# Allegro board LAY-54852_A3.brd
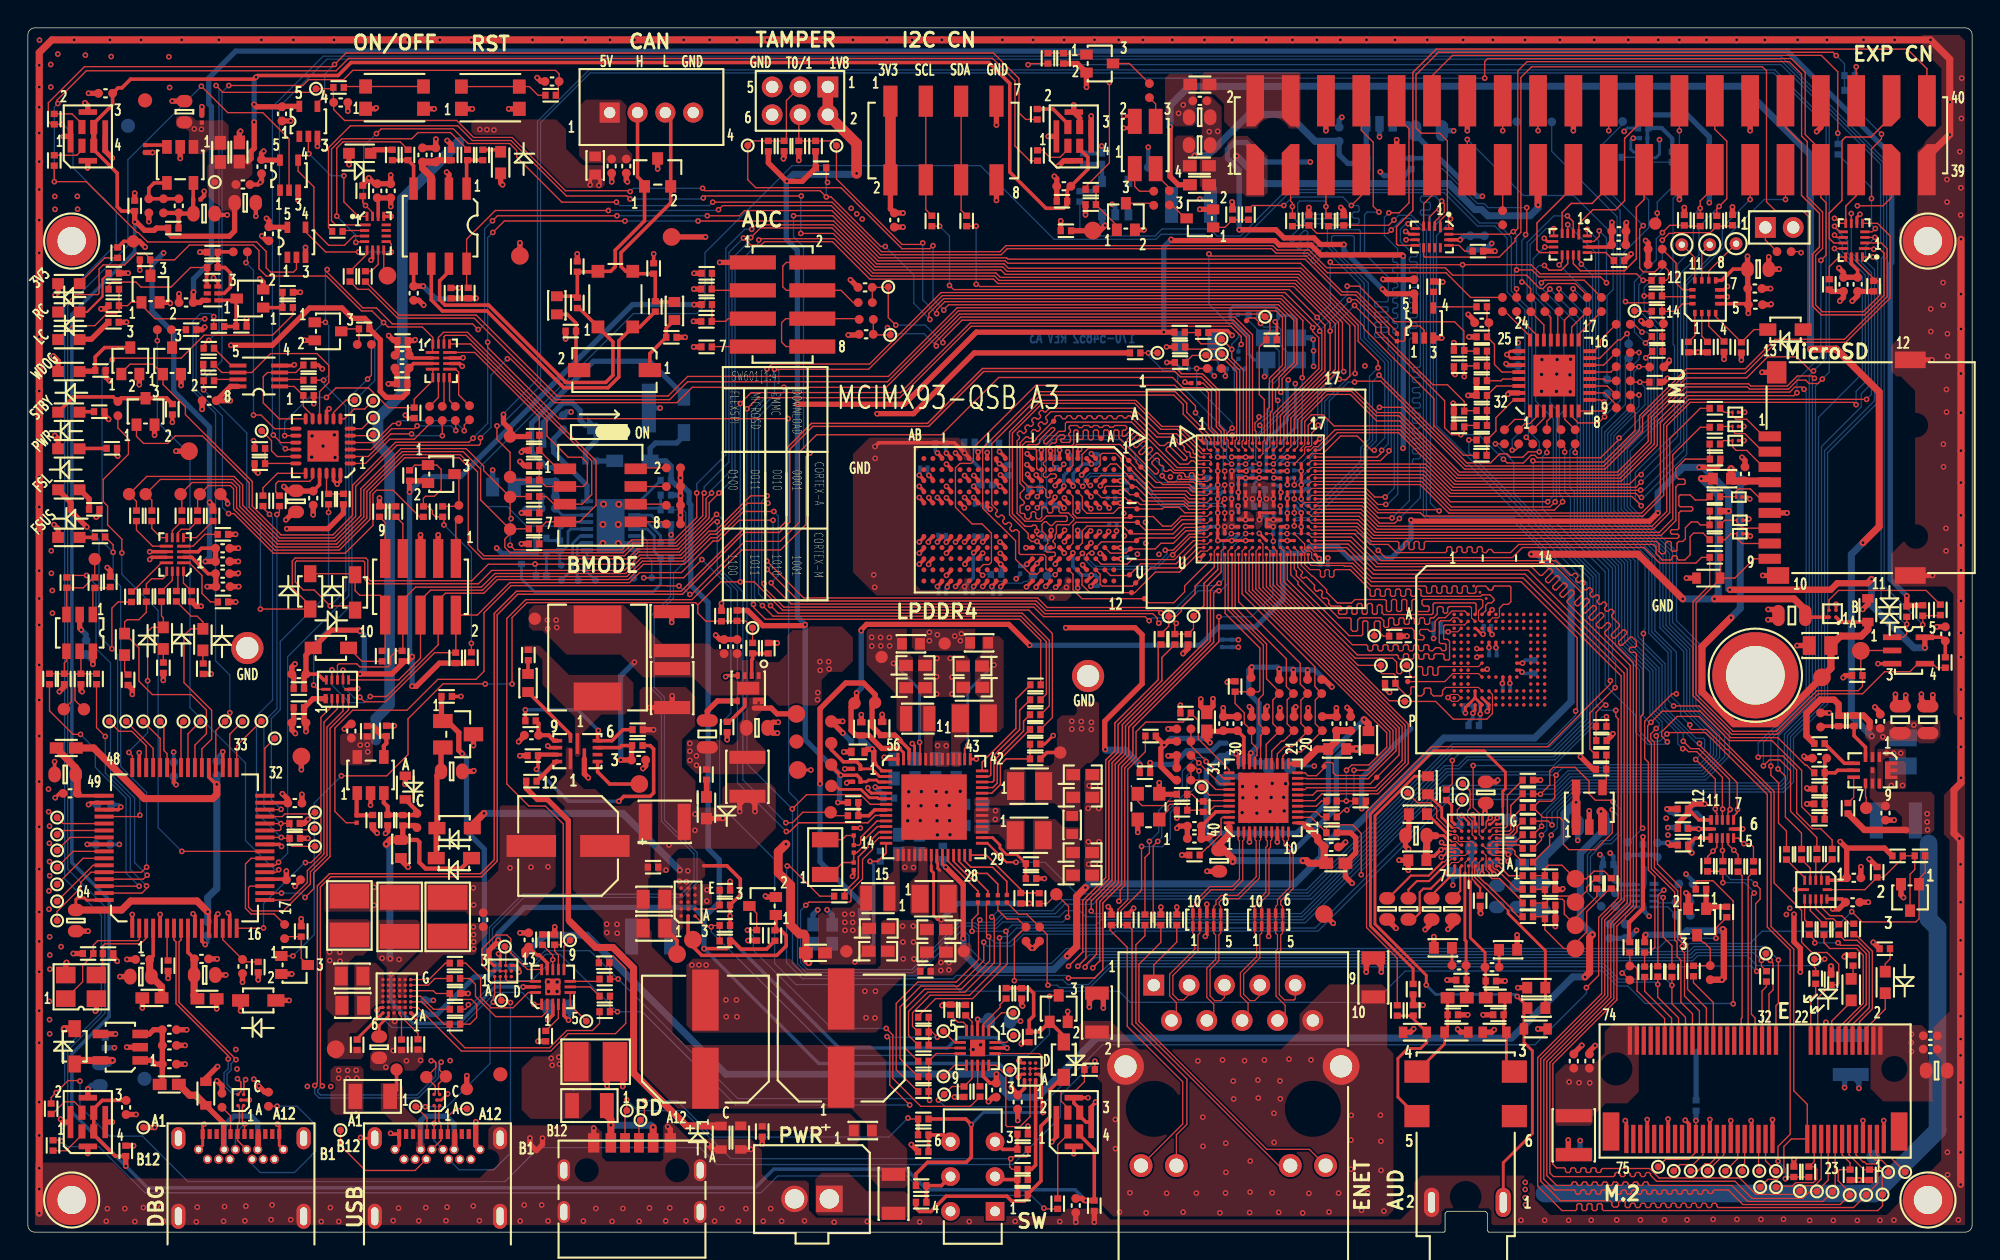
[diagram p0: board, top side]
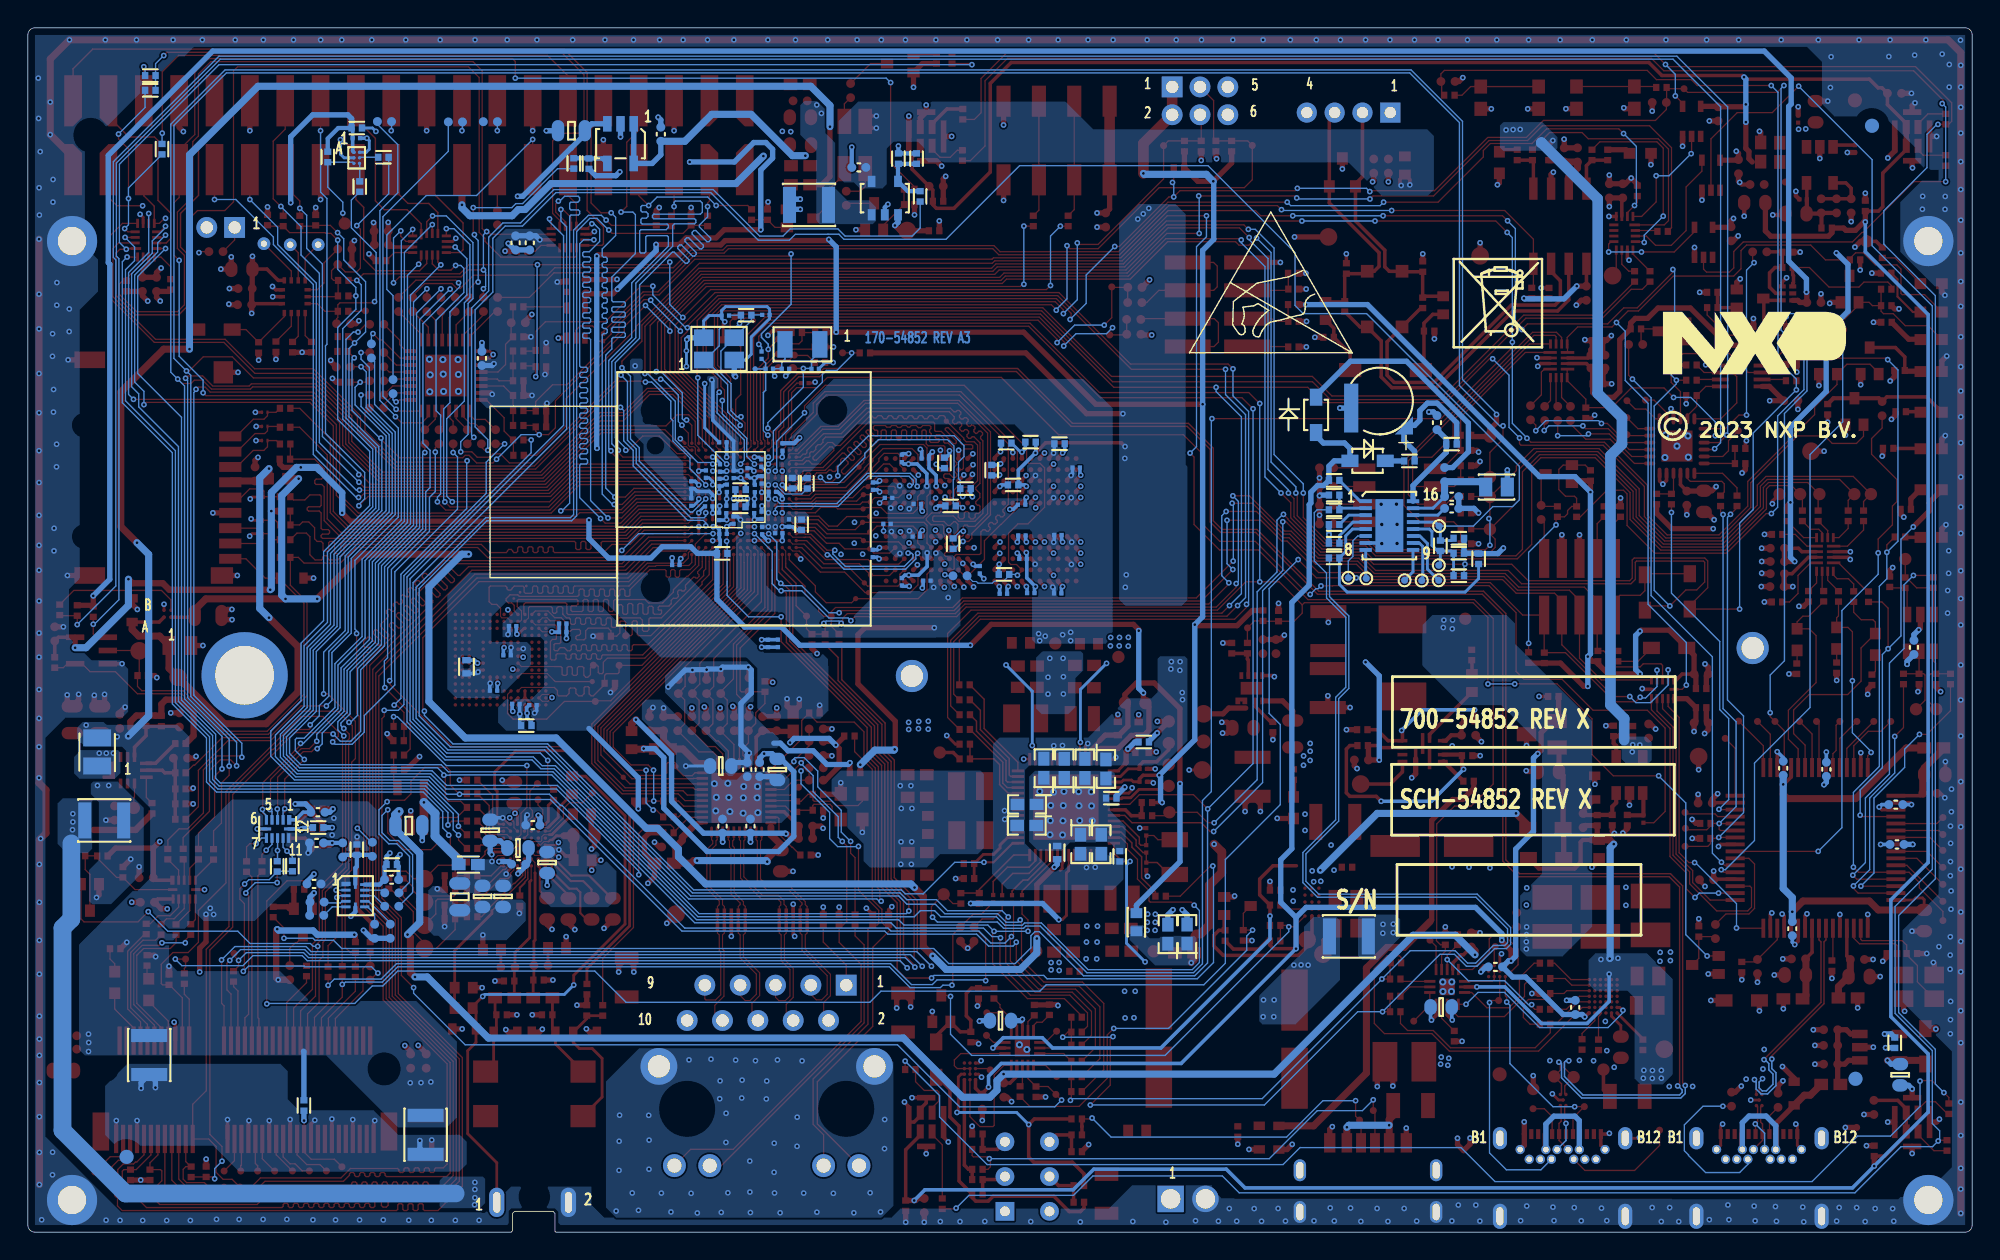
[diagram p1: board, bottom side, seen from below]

Outline 139.7 x 86.56 mm; copper layers: TOP, L2_GND, L3_PWR, BOTTOM. Coordinates in mm from the lower left corner of the outline.
Outline path: 0,86.05 arc(0.15,86.41) 0.51,86.56 139.19,86.56 arc(139.55,86.41) 139.7,86.05 139.7,0.51 arc(139.55,0.15) 139.19,0 104.97,0 104.87,0.11 104.87,1.36 104.72,1.5 101.97,1.5 101.83,1.36 101.83,0.08 101.75,0 0.51,0 arc(0.15,0.15) 0,0.51 0,86.05

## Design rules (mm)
constraint set DEFAULT: min track width 0.091
net group DIFFPAIR56: nets USB1_DN USB1_DP
net group DIFFPAIR57: nets ETH1_TRX3_N ETH1_TRX3_P
net group DIFFPAIR58: nets ETH1_TRX2_N ETH1_TRX2_P
net group DIFFPAIR59: nets ETH1_TRX1_N ETH1_TRX1_P
net group DIFFPAIR60: nets ETH1_TRX0_N ETH1_TRX0_P
net group DIFFPAIR61: nets FT_USB_DN FT_USB_DP
net group DIFFPAIR62: nets USB_DBG_DN USB_DBG_DP
net group DIFFPAIR63: nets USBC_DN USBC_DP
net group M-DDR-ADDRESS: nets DRAM_CA0_A DRAM_CA1_A DRAM_CA2_A DRAM_CA3_A DRAM_CA4_A DRAM_CA5_A DRAM_CK_C_A DRAM_CK_T_A DRAM_CKE0_A DRAM_CKE1_A DRAM_NCS0_A DRAM_NCS1_A
net group M-DDR-DATA0: nets DRAM_DATA0_A DRAM_DATA1_A DRAM_DATA2_A DRAM_DATA3_A DRAM_DATA4_A DRAM_DATA5_A DRAM_DATA6_A DRAM_DATA7_A DRAM_DMI0_A DRAM_SDQS0_C_A DRAM_SDQS0_T_A
net group M-DDR-DATA1: nets DRAM_DATA8_A DRAM_DATA9_A DRAM_DATA10_A DRAM_DATA11_A DRAM_DATA12_A DRAM_DATA13_A DRAM_DATA14_A DRAM_DATA15_A DRAM_DMI1_A DRAM_SDQS1_C_A DRAM_SDQS1_T_A
net group M-GPIO: nets GPIO_IO00 GPIO_IO01 GPIO_IO02 GPIO_IO03 GPIO_IO04 GPIO_IO05 GPIO_IO06 GPIO_IO07 GPIO_IO08 GPIO_IO09 GPIO_IO10 GPIO_IO11 GPIO_IO12 GPIO_IO14 GPIO_IO15 GPIO_IO16 GPIO_IO17 GPIO_IO18 GPIO_IO19 GPIO_IO20 GPIO_IO21
net group M-RX: nets ENET1_RD0 ENET1_RD1 ENET1_RD2 ENET1_RD3 ENET1_RX_CTL ENET1_RXC
net group M-TX: nets ENET1_TD0 ENET1_TD1 ENET1_TD2 ENET1_TD3 ENET1_TX_CTL ENET1_TXC
net group SD1-EMMC: nets SD1_CLK SD1_CMD SD1_DATA0 SD1_DATA1 SD1_DATA2 SD1_DATA3 SD1_DATA4 SD1_DATA5 SD1_DATA6 SD1_DATA7 SD1_STROBE
net group SD3: nets SD3_CLK SD3_CMD SD3_DATA0 SD3_DATA1 SD3_DATA2 SD3_DATA3

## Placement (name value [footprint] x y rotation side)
BH901  SMTSO-M2.5-5ET  [MH244-166T_202H]  124.12 40.03 180 top
BH1901  MH142B-80T  [MH142P080]  136.52 2.31 0 top
BH1902  MH142B-80T  [MH142P080]  3.15 71.24 0 top
BH1903  MH142B-80T  [MH142P080]  3.15 2.31 0 top
BH1904  MH142B-80T  [MH142P080]  136.52 71.24 90 top
BT1001  ML414H  [BATTERY_4P8SQ_S]  42.59 59.74 270 bottom
C10  0.1uF  [0402_CC]  75.85 77.16 90 bottom
C22  0.1uF  [CC0402_25]  113.57 25.34 180 bottom
C23  0.1uF  [CC0402_25]  119.14 25.03 0 bottom
C38  100UF  [1210_CC]  83.57 73.83 0 bottom
C101  1uF  [0201_CC]  89.97 54.92 90 bottom
C102  0.22UF  [0201_CC]  89.76 56.77 0 bottom
C104  10uF  [0402_CC]  88.49 53.37 180 bottom
C105  1uF  [0201_CC]  86.52 42.31 270 bottom
C106  1uF  [0201_CC]  89.51 51.95 270 bottom
C107  1uF  [0201_CC]  89.48 53.47 90 bottom
C108  10uF  [0402_CC]  88.51 52.14 0 bottom
C109  1uF  [0201_CC]  85.81 42.32 270 bottom
C110  1uF  [0201_CC]  87.51 51.95 270 bottom
C111  1uF  [0201_CC]  87.46 53.45 90 bottom
C115  1uF  [0201_CC]  86.98 51.52 270 bottom
C116  1uF  [0201_CC]  89 51.18 270 bottom
C118  1uF  [0201_CC]  92.03 53.7 90 bottom
C119  1uF  [0201_CC]  92.03 52.48 270 bottom
C129  1uF  [0201_CC]  89.75 50.19 180 bottom
C130  1uF  [0201_CC]  90.98 54.48 90 bottom
C131  1uF  [0201_CC]  90.78 52.17 0 bottom
C132  1uF  [0201_CC]  93.14 47.95 180 bottom
C133  1uF  [0201_CC]  85.48 56.43 90 bottom
C136  10uF  [0402_CC]  84.11 50.84 270 bottom
C137  1uF  [0201_CC]  86.94 50.43 270 bottom
C138  1uF  [0201_CC]  86.21 53.21 180 bottom
C139  1uF  [0201_CC]  85.75 50.24 180 bottom
C140  1uF  [0201_CC]  85.01 50.97 270 bottom
C142  22uF  [CC0603]  56.41 21.42 90 bottom
C143  22uF  [CC0603]  57.79 21.41 90 bottom
C144  1uF  [0201_CC]  88 54.65 270 bottom
C145  1uF  [0201_CC]  90 53.88 270 bottom
C146  1uF  [0201_CC]  90.03 51.45 270 bottom
C151  10uF  [0402_CC]  84.77 53.83 270 bottom
C152  1uF  [0201_CC]  86.97 54.07 90 bottom
C153  1uF  [0201_CC]  87 55.28 90 bottom
C155  1uF  [0201_CC]  88.98 54.47 270 bottom
C201  10uF  [0402_CC]  67.66 56.79 0 bottom
C202  10uF  [0402_CC]  68.91 53.71 0 bottom
C203  1uF  [0201_CC]  75.22 55.61 0 bottom
C204  1uF  [0201_CC]  75.1 46.83 0 bottom
C205  1uF  [0201_CC]  67.64 45.93 0 bottom
C206  10uF  [0402_CC]  70.44 54.77 90 bottom
C207  10uF  [0402_CC]  69.4 56.71 180 bottom
C208  1uF  [0201_CC]  79 48.78 270 bottom
C209  1uF  [0201_CC]  68.2 48.39 0 bottom
C210  1uF  [0201_CC]  68.3 52.29 180 bottom
C211  1uF  [0201_CC]  71.3 47.61 270 bottom
C212  1uF  [0201_CC]  69.61 45.89 180 bottom
C213  1uF  [0201_CC]  68.28 50.07 180 bottom
C214  1uF  [0201_CC]  78.98 53.62 90 bottom
C215  10uF  [0402_CC]  65.58 56.67 180 bottom
C216  1uF  [0201_CC]  76.9 46.75 270 bottom
C217  1uF  [0201_CC]  75.86 49.99 180 bottom
C218  1uF  [0201_CC]  76.9 55.61 90 bottom
C219  1uF  [0201_CC]  64.38 54.96 180 bottom
C220  1uF  [0201_CC]  65.69 50.11 180 bottom
C221  1uF  [0201_CC]  75.79 52.34 180 bottom
C222  1uF  [0201_CC]  65.71 45.91 180 bottom
C301  4.7uF  [CC1210]  40.8 12.25 0 top
C302  100uF  [CCE8P3X8P3]  58.44 13.95 90 top
C303  100uF  [CCE8P3X8P3]  48.68 13.87 90 top
C304  0.22uF  [0402_CC]  71.94 14.03 270 top
C305  0.1uF  [CC0402_25]  71.12 9.35 270 top
C306  2.2uF  [0402_CC]  67.39 15.96 270 top
C307  4.7uF  [CC0603_OV]  69.81 15.2 0 bottom
C309  0.1uF  [CC0402_25]  69.58 10.21 90 top
C401  0.1uF  [0402_CC]  84.45 64.66 0 top
C402  18pF  [0201_CC]  85.27 62.05 180 bottom
C403  18pF  [0201_CC]  83.13 62.05 180 bottom
C404  12pF  [0201_CC]  89.58 65.88 0 bottom
C405  12pF  [0201_CC]  86.67 65.93 180 bottom
C406  0.1uF  [CC0402_25]  32.72 22.46 90 top
C407  0.01UF  [0402_CC]  23.66 13.47 270 top
C408  0.1uF  [CC0402_25]  28.52 16.15 90 bottom
C409  1000pF  [0402_CC]  26.85 13.47 270 top
C410  4.7uF  [CC0603_OV]  25.24 13.29 270 top
C411  4.7uF  [CC0603_OV]  38.15 16.18 0 bottom
C412  2.2uF  [0402_CC]  30.09 38.51 0 top
C413  0.1uF  [CC0402_25]  35.99 21 270 top
C414  1uF  [CC0603_OV]  30.45 33.12 0 top
C418  0.1uF  [CC0402_25]  34.25 19.07 0 bottom
C501  4.7uF  [CC0402_TOL0P15]  108.19 40.64 90 bottom
C502  0.22UF  [0201_CC]  105.27 41.46 0 bottom
C503  0.22UF  [0201_CC]  106.24 38.92 180 bottom
C504  10uF  [0402_CC]  103.89 36.41 180 bottom
C505  0.22UF  [0201_CC]  103.41 37.88 0 bottom
C506  0.22UF  [0201_CC]  104.87 43.56 180 bottom
C507  0.22UF  [0201_CC]  104.63 37.98 0 bottom
C508  0.22UF  [0201_CC]  101.27 43.13 180 bottom
C509  1uF  [0201_CC]  101.27 43.75 180 bottom
C510  16pF  [0402_CC]  82.93 31.47 180 top
C511  0.1uF  [CC0402_25]  87.12 33.25 270 bottom
C512  4.7uF  [CC0603_OV]  85.85 33.25 270 bottom
C513  1uF  [CC0402_25]  95.04 36.55 90 top
C514  0.1uF  [CC0402_25]  94.02 36.55 90 top
C515  1uF  [CC0402_25]  89.79 29.18 90 bottom
C516  0.1uF  [CC0402_25]  83.82 28.3 180 top
C517  0.1uF  [CC0402_25]  83.82 29.18 180 top
C518  0.1uF  [CC0402_25]  87.78 29.18 90 bottom
C519  16pF  [0402_CC]  86.74 39.22 90 top
C520  470PF  [0402_CC]  81.41 22.45 90 top
C521  470PF  [0402_CC]  78.99 22.45 90 top
C701  10uF  [CC0603]  64.06 27.88 270 bottom
C702  10uF  [CC0603]  62.57 27.88 270 bottom
C703  22uF  [CC0603]  67.87 40.69 180 top
C704  1uF  [0402_CC]  61.25 27.02 90 bottom
C705  22uF  [CC0603]  67.89 39.16 180 top
C706  1uF  [0402_CC]  61.86 31.2 0 bottom
C707  22uF  [CC0603]  75.8 31.26 0 top
C708  22uF  [CC0603]  75.8 32.88 0 top
C709  10uF  [CC0603]  67.91 30.74 0 bottom
C710  22uF  [CC0603]  75.78 25.66 0 top
C711  22uF  [CC0603]  75.78 27.29 0 top
C712  10uF  [CC0603]  67.93 29.23 0 bottom
C713  10uF  [CC0603]  66.7 33.34 90 bottom
C714  22uF  [CC0603]  65.28 21.75 180 top
C715  22uF  [CC0603]  65.28 20.13 180 top
C716  18pF  [0201_CC]  59.34 28.78 90 top
C717  18pF  [0201_CC]  59.34 26.3 270 top
C718  10uF  [CC0603]  65.23 33.34 90 bottom
C719  22uF  [CC0603]  61.1 20.2 0 top
C720  22uF  [CC0603]  61.13 21.83 0 top
C721  10uF  [CC0603]  63.75 33.33 90 bottom
C722  22uF  [CC0603]  63.79 39.13 0 top
C723  22uF  [CC0603]  63.78 40.73 0 top
C724  1uF  [0402_CC]  64.49 18.75 0 top
C725  4.7uF  [CC0402_TOL0P15]  65.74 27.28 90 bottom
C726  10uF  [CC0603]  62.24 33.29 270 bottom
C727  1uF  [0201_CC]  59.56 32.37 180 top
C728  1uF  [0201_CC]  59.56 33.3 180 top
C729  4.7uF  [CC0402_TOL0P15]  61.38 36.2 90 top
C730  4.7uF  [CC0402_TOL0P15]  59.65 34.52 180 top
C731  4.7uF  [CC0402_TOL0P15]  59.89 36.18 90 top
C801  0.1uF  [CC0402_25]  107.07 62.8 90 bottom
C802  0.1uF  [CC0402_25]  99.6 67.95 90 top
C803  0.1uF  [CC0402_25]  104.46 65.37 180 top
C804  1uF  [CC0402_25]  131.47 68.12 270 top
C805  1uF  [CC0402_25]  114.3 70.97 0 top
C806  0.1uF  [CC0402_25]  114.32 71.94 0 top
C807  0.1uF  [CC0402_25]  130.45 68.12 270 top
C808  1uF  [CC0402_25]  104.65 71.11 270 bottom
C809  0.1uF  [CC0402_25]  103.64 71.11 270 bottom
C901  0.22uF  [0402_CC]  35.96 41.48 90 top
C902  0.1uF  [CC0402_25]  43.88 33.94 0 top
C903  100UF  [1210_CC]  46.26 43.2 90 top
C904  100UF  [1210_CC]  46.3 39.11 270 top
C905  100uF  [CASE_D_AL]  38.82 27.76 180 top
C906  0.22uF  [0402_CC]  52.77 7.23 270 top
C907  1uF  [CC0402_25]  36.18 35.72 180 top
C908  1uF  [CC0402_25]  50.02 42.09 90 top
C910  100UF  [1210_CC]  51.7 32.73 270 top
C911  1uF  [CC0402_25]  50.96 42.09 90 top
C912  0.1uF  [CC0402_25]  136.69 13.15 0 top
C913  0.1uF  [CC0402_25]  111.08 12.29 90 top
C914  0.1uF  [CC0402_25]  112.2 12.29 90 top
C915  10uF  [CC0603_OV]  137.15 11.61 0 top
C916  100UF  [1210_CC]  111.07 6.96 270 top
C917  100UF  [1210_CC]  111.12 7 270 bottom
C918  100UF  [1210_CC]  130.98 12.73 270 bottom
C920  1uF  [CC0402_25]  118.86 30.18 180 bottom
C921  0.01UF  [0402_CC]  118.91 30.42 180 top
C922  1uF  [CC0402_25]  118.96 27.98 180 bottom
C923  0.01UF  [0402_CC]  118.92 27.82 180 top
C928  4.7uF  [CC0603_OV]  52.39 36.25 0 top
C930  1uF  [CC0402_25]  79.99 76.53 0 bottom
C931  0.1uF  [0402_CC]  44.92 26.23 0 top
C932  10uF  [1210_CC]  44.78 21.26 0 bottom
C933  10uF  [1210_CC]  45.76 29.49 0 top
C955  1.0UF  [0402_CC]  116.07 79.36 180 bottom
C956  0.22UF  [0201_CC]  116.1 78.63 180 bottom
C1019  0.1uF  [CC0402_25]  137.77 43 90 top
C1020  22uF  [CC0805_OV]  126.75 44.32 180 top
C1021  0.1uF  [CC0402_25]  37.4 52.02 180 bottom
C1022  0.1uF  [CC0402_25]  38.45 58.19 90 bottom
C1023  47uF  [0805_CC]  34.18 53.55 180 bottom
C1024  0.1uF  [CC0402_25]  37.4 52.87 180 bottom
C1201  4.7uF  [CC0603_OV]  104.75 31.6 90 top
C1202  0.1uF  [CC0402_25]  104.44 26.45 0 bottom
C1204  4.7uF  [CC0603_OV]  105.56 24.13 270 bottom
C1205  4.7uF  [CC0603_OV]  107.03 24.13 270 bottom
C1207  4.7uF  [CC0603_OV]  106.48 28.89 270 bottom
C1208  1.0 UF  [0603_CC]  108.38 17.57 180 top
C1209  4.7uF  [CC0603_OV]  99.75 28.49 180 top
C1210  4.7uF  [CC0603_OV]  97.67 23.24 270 top
C1217  15PF  [0402_CC]  109.37 25.62 0 top
C1218  15PF  [0402_CC]  113.77 25.07 270 top
C1219  22uF  [CC0805_OV]  112.32 29.22 180 bottom
C1221  15PF  [0402_CC]  109.38 22.53 180 top
C1223  15PF  [0402_CC]  109.37 24.62 0 top
C1224  15PF  [0402_CC]  112.73 25.05 270 top
C1227  15PF  [0402_CC]  109.38 23.51 180 top
C1230  22uF  [CC0805_OV]  108.67 24.1 270 bottom
C1231  4.7uF  [CC0603_OV]  104.48 27.61 0 bottom
C1301  1uF  [CC0402_25]  7.06 8.97 270 top
C1302  4.7uF  [CC0603_OV]  15.62 73.98 0 top
C1303  0.1uF  [CC0402_25]  15.45 75.3 0 top
C1304  0.01UF  [0402_CC]  7.04 5.84 90 top
C1307  1uF  [CC0402_25]  75.29 1.91 270 top
C1308  0.01UF  [0402_CC]  76.63 1.9 270 top
C1309  1uF  [CC0402_25]  5.58 81.85 180 top
C1310  0.01UF  [0402_CC]  7.68 73.77 90 top
C1317  1uF  [CC0402_25]  74.44 75.18 180 top
C1318  0.01UF  [0402_CC]  74.3 74.1 180 top
C1319  4.7uF  [CC0603_OV]  11.25 80.53 90 top
C1320  0.1uF  [0201_CC]  12.5 80.01 90 top
C1321  56pF  [CC0402_25]  10.85 73.77 90 top
C1322  4.7uF  [CC0603_OV]  12.66 73.21 0 top
C1323  0.1uF  [0201_CC]  12.15 74.23 0 top
C1324  0.1uF  [CC0402_25]  17.32 71.76 270 top
C1325  0.1uF  [CC0402_25]  16.79 76.58 270 top
C1401  4.7uF  [CC0603_OV]  124.32 69.22 0 top
C1402  10uF  [CC0603_OV]  84.19 78.13 0 top
C1403  0.1uF  [CC0402_25]  124.13 66.66 0 top
C1404  0.1uF  [CC0402_25]  124.09 67.82 0 top
C1405  0.1uF  [CC0402_25]  94.22 78.91 90 bottom
C1406  10uF  [CC0603_OV]  84.19 80.13 0 top
C1407  0.1uF  [CC0402_25]  84.21 81.31 0 top
C1408  0.1uF  [CC0402_25]  13.58 33.34 90 bottom
C1409  0.1uF  [CC0402_25]  10.17 12.08 0 top
C1410  100PF  [CC0402_25]  37.66 82.71 180 top
C1411  100PF  [CC0402_25]  22.48 81.2 0 top
C1412  1uF  [CC0402_25]  62.26 72.75 270 top
C1413  100PF  [CC0402_25]  60.16 67.91 180 top
C1414  100PF  [CC0402_25]  60.23 64.53 180 top
C1415  4.7uF  [CC0603_OV]  8.12 18.37 180 top
C1416  0.1uF  [CC0402_25]  8.25 19.6 180 top
C1417  0.1uF  [CC0402_25]  5.4 27.87 0 bottom
C1418  0.1uF  [CC0402_25]  5.49 30.73 0 bottom
C1419  0.1uF  [CC0402_25]  10.48 33.27 90 bottom
C1420  0.1uF  [CC0402_25]  19.08 25.33 0 top
C1421  4.7uF  [CC0603_OV]  2.69 32.9 180 top
C1422  0.1uF  [CC0402_25]  3.04 31.54 180 top
C1423  0.1uF  [CC0402_25]  19.18 30.84 0 top
C1424  1uF  [CC0402_25]  26.89 62.11 180 top
C1425  0.01UF  [0402_CC]  26.9 60.97 180 top
C1426  1uF  [CC0402_25]  26.89 63.03 180 top
C1427  0.01UF  [0402_CC]  26.92 64.09 180 top
C1428  27 PF  [0402_CC]  4.33 20.03 180 top
C1429  0.1uF  [CC0402_25]  4.18 42.03 90 bottom
C1430  27 PF  [0402_CC]  5.77 20.02 0 top
C1431  0.1uF  [CC0402_25]  15.43 19.09 270 top
C1432  0.1uF  [CC0402_25]  13.03 59.76 180 top
C1433  0.1uF  [CC0402_25]  11.37 66.82 180 top
C1434  1uF  [CC0402_25]  19.47 36.61 180 top
C1435  0.01UF  [0402_CC]  19.47 37.7 180 top
C1436  1uF  [CC0402_25]  19.47 40.11 180 top
C1437  0.01UF  [0402_CC]  19.47 39.07 180 top
C1448  0.22uF  [0402_CC]  31.87 41.3 90 top
C1449  0.01UF  [0402_CC]  29.8 51.79 270 top
C1460  4.7uF  [CC0603_OV]  19.27 52.53 270 top
C1461  0.1uF  [CC0402_25]  20.5 52.76 270 top
C1462  0.1uF  [CC0402_25]  18.26 80.38 270 top
C1501  1uF  [CC0402_25]  29.31 77.42 90 top
C1502  0.1uF  [CC0402_25]  28.36 77.42 90 top
C1503  1uF  [CC0402_25]  27.72 67.49 270 top
C1504  56PF  [0402_CC]  39.48 69.4 270 top
C1505  1uF  [CC0402_25]  41.95 76.62 270 top
C1506  0.1uF  [CC0402_25]  43 76.62 270 top
C1507  56PF  [0402_CC]  39.01 64.76 180 top
C1508  56PF  [0402_CC]  46.24 64.32 0 top
C1509  56PF  [0402_CC]  44.96 69.27 90 top
C1703  0.1uF  [CC0402_25]  25.11 74.84 90 top
C1704  0.1uF  [CC0402_25]  26.07 74.84 90 top
C1719  1uF  [CC0402_25]  14.02 46.4 0 top
C1720  0.1uF  [CC0402_25]  13.99 47.33 0 top
C1721  1uF  [CC0402_25]  13.99 48.2 0 top
C1722  0.1uF  [CC0402_25]  13.99 49.16 0 top
C1723  4.7uF  [CC0603_OV]  3.45 22.4 270 top
C1724  0.1uF  [CC0402_25]  12.92 21.81 270 bottom
C1725  1uF  [CC0402_25]  10.17 13.42 0 top
C1726  1uF  [CC0402_25]  10.17 14.55 0 top
C1727  4.7uF  [CC0603_OV]  5.17 11.31 270 bottom
C1728  4.7uF  [CC0603_OV]  12.71 18.49 0 top
C1729  0.1uF  [CC0402_25]  12.48 19.64 0 top
C1730  0.22uF  [0402_CC]  5.56 13.61 270 bottom
C1731  47uF  [0805_CC]  128.78 42.16 180 top
C1732  0.1uF  [CC0402_25]  123.38 54.5 90 top
C1733  0.1uF  [CC0402_25]  23.25 36.02 90 top
C1734  4.7uF  [CC1210]  26.71 22.66 90 top
C1735  10UF  [CC1210]  23.11 22.76 90 top
C1736  47UF  [CC1210]  30.17 22.66 90 top
C1737  2.2uF  [0402_CC]  37.21 14.09 90 top
C1738  0.22uF  [0402_CC]  82.55 22.45 90 top
C1739  1uF  [CC0402_25]  86.91 36.55 90 top
C1740  0.1uF  [CC0402_25]  85.89 36.55 90 top
C1741  16pF  [0402_CC]  82.93 30.33 180 top
C1742  4.7uF  [CC0603_OV]  85.6 26.7 270 top
C1743  0.1uF  [CC0402_25]  93.65 27.69 0 top
C1744  1000pF  [1206_CC]  76.82 15.79 270 top
C1745  4.7uF  [CC0603_OV]  89.92 33.5 0 bottom
C1746  0.1uF  [CC0402_25]  88.01 33.25 270 bottom
C1747  100UF  [1210_CC]  134.21 29.59 180 bottom
C1748  0.1uF  [CC0402_25]  133.47 30.12 270 top
C1749  1000pF  [0402_CC]  131.22 36.76 270 top
C1750  22uF  [CC0805_OV]  134.53 36.83 90 top
C1751  22uF  [CC0805_OV]  136.51 36.83 90 top
C1752  0.1uF  [CC0402_25]  133.1 36.72 90 top
C1753  1000pF  [0402_CC]  128.73 35.12 180 top
C1754  0.1uF  [CC0402_25]  128.73 34.07 180 top
C1755  0.1uF  [CC0402_25]  131.2 25.47 0 top
C1756  0.1uF  [CC0402_25]  131.11 23.71 0 top
C1757  0.1uF  [CC0402_25]  136.69 14.12 0 top
C1761  2.2uF  [CC0603_OV]  99.2 23.24 90 top
C1762  2.2uF  [CC0603_OV]  100.86 23.23 270 top
C1763  2.2uF  [CC0603_OV]  102.39 23.24 270 top
C1764  4.7uF  [CC0603_OV]  102.39 26.57 270 bottom
C1765  0.1uF  [CC0402_25]  103.42 29.25 180 bottom
C1769  0.1uF  [CC0402_25]  102.83 19.18 180 top
C1770  0.1uF  [CC0402_25]  105.21 19.05 0 top
C1771  1000pF  [0402_CC]  102.38 15.62 0 top
C1772  1000pF  [0402_CC]  105.66 15.62 180 top
C1787  1.0 UF  [0603_CC]  99.88 30.04 0 top
C1788  1.0 UF  [0603_CC]  100.6 32.12 90 top
C1789  22uF  [CC0805_OV]  100.64 79.17 0 bottom
C1792  1uF  [0402_CC]  113.55 26.42 180 bottom
D301  BAT54HT1  [SOD323]  74.44 12.4 0 top
D302  BZX585-B3V3  [SOD523]  27.12 31.95 90 top
D401  BAT54HT1  [SOD323]  30.67 29.04 270 top
D402  BAT54HT1  [SOD323]  30.61 26.88 270 top
D601  LED GREEN  [LED_0603]  2.95 68.17 180 top
D901  BZX585-B3V3  [SOD523]  49.81 6.79 270 top
D902  LED RED  [LED_0603]  48.76 30.51 270 top
D1003  ESD5B5.0ST1G  [DIODE2_SOD523]  132.21 44.7 90 top
D1004  ESD5B5.0ST1G  [DIODE2_SOD523]  120.74 47.01 180 top
D1005  PESD5V0R1BSF  [DSN0603-2]  122.68 56.9 0 top
D1006  PESD5V0R1BSF  [DSN0603-2]  122.94 52.83 0 top
D1007  PESD5V0R1BSF  [DSN0603-2]  123 51.17 0 top
D1008  PESD5V0R1BSF  [DSN0603-2]  123 50.2 0 top
D1009  PESD5V0R1BSF  [DSN0603-2]  122.68 58.93 0 top
D1010  PESD5V0R1BSF  [DSN0603-2]  122.68 57.91 0 top
D1011  BAT54HT1  [SOD323]  47.14 58.74 0 bottom
D1012  BAT54HT1  [SOD323]  43.44 55.44 90 bottom
D1401  BAT54HT1  [SOD323]  126.29 64.87 270 top
D1402  RGB  [LED4_3P4X3_SM]  80.28 78.14 180 top
D1403  LED_ORANGE  [LED_0603_11MIL]  12.58 42.59 90 top
D1404  LED GREEN  [LED_0603]  6.95 42.25 90 top
D1405  LED GREEN  [LED_0603]  2.95 53.36 180 top
D1406  LED_ORANGE  [LED_0603_11MIL]  9.73 42.69 90 top
D1407  NSR0320  [SOD323]  21.77 41.99 90 top
D1408  NSR0320  [SOD323]  23.51 45.98 180 top
D1409  NSR0320  [SOD323]  20.29 46.06 180 top
D1410  LED RED  [LED_0603]  2.95 56.3 180 top
D1411  LED_ORANGE  [LED_0603_11MIL]  2.95 49.94 180 top
D1412  LED RED  [LED_0603]  2.95 64.15 180 top
D1413  LED GREEN  [LED_0603]  2.95 66.13 180 top
D1414  LED_ORANGE  [LED_0603_11MIL]  2.95 61.85 180 top
D1415  LED_ORANGE  [LED_0603_11MIL]  2.95 58.93 180 top
D1501  LED GREEN  [LED_0603]  23.85 77.54 0 top
D1502  LED_ORANGE  [LED_0603_11MIL]  33.97 76.88 90 top
D1503  PESD2CANFD24V-T  [SOT23_A]  45.25 76.17 0 top
D1703  NSR0320  [SOD323]  16.56 16.66 270 top
D1704  NSR0320  [SOD323]  3.36 13.36 180 top
D1705  LED GREEN  [LED_0603]  133.46 17.95 270 top
D1706  LED_ORANGE  [LED_0603_11MIL]  131.01 17.43 270 top
F301  7A  [FUSE_3P4X1P8]  40.35 9.1 180 top
F401  7A  [FUSE_3P4X1P8]  24.78 9.76 180 top
J301  USB 6 TYPE C  [USB6P_TYPEC_RA_SM]  43.41 3.18 0 top
J501  RJ-45  [CON_RJ45_10_2LED_TH]  80.9 17.75 180 top
J901  CON_1X2  [CON2_2P5_7P96X5P96_TH]  57.59 2.39 270 top
J1002  CONN_SD_CARD 9  [CON9_SDCARD_1P1MM]  132.41 54.95 90 top
J1101  23K2 0101#LCP-872-2LF-L22-S22  [CON24_USB_TYPEC_RA_SMT_TH_2P2L]  32.48 5.94 0 top
J1201  KJ366EYS  [CON6_AUDIOJACK_RA_TH]  106.01 2.14 90 top
J1401  TSM-120-01-F-DV-A  [HDR220_TSM_A_SM]  112.32 78.84 90 top
J1403  HDR 2X3  [HDR203_TMM_210H]  57.48 82.31 180 top
J1405  HDR_2X4  [HDR204_TMM_SM]  54.23 66.68 0 top
J1406  SSM-104-L-DV  [CON_2X4_SKT_100_SM]  65.79 78.46 90 top
J1501  CON 1X4 PLUG  [CON1X4_2MM_TH_303H]  41.81 80.47 180 top
J1704  FTSH-105-01-L-DV-K  [HDR205_10M_50_SM_K]  28.21 46.39 180 top
J1707  M.2 SKT KEY-E  [CON_75_0P5_22X9_RA1]  124.1 10.06 180 top
J1708  23K2 0101#LCP-872-2LF-L22-S22  [CON24_USB_TYPEC_RA_SMT_TH_2P2L]  18.36 5.94 0 top
J1710  HDR 1X2  [HDR102_TMM]  124.84 72.21 180 top
L102  1.0K OHM@100MHz  [IND_0603]  56.59 20.08 180 top
L501  120 OHM  [IND_0603]  84.71 36.68 270 top
L502  120 OHM  [IND_0603]  93.98 26.52 180 top
L701  0.47uH  [IND_SPH2520]  68.01 36.93 0 top
L702  0.47uH  [IND_SPH2520]  71.98 32.06 0 top
L703  0.47uH  [IND_SPH2520]  71.95 28.53 0 top
L704  0.47uH  [IND_SPH2520]  65.12 23.96 0 top
L705  0.47uH  [IND_2016A]  61.08 24.01 180 top
L706  0.47uH  [IND_2016A]  63.94 36.91 180 top
L901  1.5uH  [IND_IHLP]  40.93 41.3 90 top
L1201  120OHM  [0603_CC]  99.84 26.73 0 top
L1202  120 OHM  [IND_0603]  102.7 16.85 180 top
L1203  120 OHM  [IND_0603]  105.44 16.84 0 top
L1205  120 OHM  [IND_0603]  108.06 26.42 180 bottom
L1301  120 OHM  [IND_0603]  15.2 77.63 270 top
L1401  120 OHM  [IND_0603]  84.18 76.65 0 top
L1402  120 OHM  [IND_0603]  84.21 82.48 180 top
L1403  120 OHM  [IND_0603]  84.18 75.28 0 top
L1404  120 OHM  [IND_0603]  2.76 34.8 180 top
L1405  120 OHM  [IND_0603]  13.82 77.61 270 top
L1501  DLW43SH510XK2  [IND_DLW43]  42.21 67.06 90 top
L1702  120 OHM  [IND_0603]  10.16 10.62 180 top
L1703  120 OHM  [IND_0603]  12.88 16.77 180 top
L1704  120 OHM  [IND_0603]  8.92 16.83 0 top
L1705  0.47uH  [IND_SPH2520]  134.72 34.52 90 bottom
NOREF  -  []  74.73 7.24 0 top
NOREF#2  -  []  92.49 48.71 90 top
NOREF#3  -  []  62.51 27.1 0 top
NOREF#4  -  []  108.19 40.16 90 top
NOREF#5  -  []  66 -0.65 90 top
NOREF#6  -  []  44.81 78.32 90 top
NOREF#7  -  []  74.01 56.26 90 top
NOREF#8  -  []  35.31 80.74 90 top
NOREF#9  -  []  124.07 9.55 0 top
NOREF#10  -  []  20.41 -2.66 90 top
NOREF#11  -  []  28.32 80.02 90 top
NOREF#12  -  []  130.99 32.15 90 top
NOREF#13  -  []  88.24 52.71 90 top
NOREF#14  -  []  74.73 78.08 0 top
NOREF#15  -  [unnamed#2]  33.95 11.35 0 top
NOREF#16  -  []  123.25 52.67 90 top
NOREF#17  -  []  135.66 50 90 top
NOREF#18  -  []  125.16 48.4 90 top
NOREF#19  -  []  17.36 41.98 0 top
NOREF#20  -  []  113.75 7.23 0 top
NOREF#21  -  []  39.3 60.56 90 top
NOREF#22  -  []  75.58 7.24 90 top
NOREF#23  -  []  115.1 13.77 0 top
NOREF#24  -  []  4.74 7.24 90 top
NOREF#25  -  []  29.1 63.84 0 top
NOREF#26  -  []  9.95 48.11 0 top
NOREF#27  -  []  127.67 23.94 0 top
NOREF#28  -  []  115.49 23.38 0 top
NOREF#29  -  []  40.17 49.04 0 top
NOREF#30  -  []  76.58 75.17 0 top
NOREF#31  -  []  61.61 27.05 0 top
NOREF#32  -  []  61.71 35.63 0 top
NOREF#33  -  []  21.2 39.92 0 top
NOREF#34  -  []  29.07 62.03 90 top
NOREF#35  -  []  131.19 32.7 90 top
NOREF#36  -  []  67.44 11.99 0 top
NOREF#37  -  []  125.16 48.4 90 top
NOREF#38  -  []  210.36 30.78 0 top
NOREF#39  -  []  131.56 211.17 90 top
NOREF#40  -  []  71.61 11.36 90 top
NOREF#41  -  []  27.03 5.24 0 top
NOREF#42  -  []  115.87 76.82 90 top
NOREF#43  -  []  84.49 48.71 0 top
NOREF#44  -  []  66.57 26.71 90 top
NOREF#45  -  []  40.66 6.42 0 top
NOREF#46  -  []  59.89 35.7 90 top
NOREF#47  -  []  60.22 34.85 0 top
NOREF#48  -  []  42.91 6.42 0 top
NOREF#49  -  []  14.89 10.11 0 top
NOREF#50  -  []  67.44 11.99 90 top
NOREF#51  -  []  28.75 63.68 90 top
NOREF#52  -  []  125.76 47.2 0 top
NOREF#53  -  []  11.59 5.24 90 top
NOREF#54  -  []  41.87 50.79 90 top
NOREF#55  -  []  41.37 49.59 0 top
NOREF#56  -  []  66.89 11.89 0 top
NOREF#57  -  []  51.76 39.09 90 top
NOREF#58  -  []  124.6 13.77 0 top
NOREF#59  -  []  38.52 16.38 90 top
NOREF#60  -  []  133.35 6.7 90 top
NOREF#61  -  []  119.22 68.78 0 top
NOREF#62  -  []  99.81 11.54 0 top
NOREF#63  -  []  107.13 63.32 0 top
NOREF#64  -  []  11.18 47.5 90 top
NOREF#65  -  [unnamed#2]  55.23 35.26 0 top
NOREF#66  -  []  77.38 46.81 0 top
NOREF#67  -  []  122.48 58.93 0 top
NOREF#68  -  []  31.15 82.34 0 top
NOREF#69  -  []  38.51 1.45 0 top
NOREF#70  -  []  68.56 32.75 90 top
NOREF#71  -  []  10.21 -2.66 0 top
NOREF#72  -  []  55.34 -0.64 0 top
NOREF#73  -  []  31.03 5.24 0 top
NOREF#74  -  []  125.11 47.55 90 top
NOREF#75  -  []  572.28 -187.35 0 top
NOREF#76  -  []  76.57 76.71 90 top
NOREF#77  -  []  61.66 27.95 0 top
NOREF#78  -  []  123.32 50.04 90 top
NOREF#79  -  []  49.63 0.05 90 top
NOREF#80  -  []  76.57 5.86 90 top
NOREF#81  -  []  25.7 5.24 90 top
NOREF#82  -  []  46.94 22.73 90 top
NOREF#83  -  []  99.96 12.74 0 top
NOREF#84  -  []  39.07 16.28 90 top
NOREF#85  -  []  63.91 56.26 0 top
NOREF#86  -  []  3.06 78.76 0 top
NOREF#87  -  []  61.36 35.6 90 top
NOREF#88  -  []  115.49 24.58 90 top
NOREF#89  -  []  128.33 0 90 top
NOREF#90  -  []  100.86 2.14 0 top
NOREF#91  -  []  125.76 47.2 90 top
NOREF#92  -  []  5.77 11.72 90 top
NOREF#93  -  []  3.89 78.08 0 top
NOREF#94  -  []  48.51 -1.65 90 top
NOREF#95  -  []  31.68 7.05 0 top
NOREF#96  -  []  64.38 54.81 90 top
NOREF#97  -  []  40.16 4.45 0 top
NOREF#98  -  []  29.39 9.5 90 top
NOREF#99  -  []  25.7 5.24 90 top
NOREF#100  -  []  25.51 17.75 90 top
NOREF#101  -  []  38.04 35.32 0 top
NOREF#102  -  []  79.68 73.47 90 top
NOREF#103  -  []  -94.96 -77.86 0 top
NOREF#104  -  []  51.01 40 0 top
NOREF#105  -  []  -316.16 275.49 0 top
NOREF#106  -  []  78.78 79.84 0 top
NOREF#107  -  []  15.1 9.9 0 top
NOREF#108  -  []  107.86 41.21 0 top
NOREF#109  -  []  136.36 47.55 90 top
NOREF#110  -  []  66.89 11.89 90 top
NOREF#111  -  []  77.18 75.52 0 top
NOREF#112  -  []  38.97 17.23 90 top
NOREF#113  -  []  26.38 5.94 0 top
NOREF#114  -  []  127.67 23.94 90 top
NOREF#115  -  []  122.48 56.9 0 top
NOREF#116  -  []  78.13 73.12 0 top
NOREF#117  -  []  110.93 64.12 0 top
NOREF#118  -  []  135.25 47.2 90 top
NOREF#119  -  []  4.31 6.16 90 top
NOREF#120  -  []  81.88 46.34 0 top
NOREF#121  -  []  122.8 50.2 0 top
NOREF#122  -  []  139.28 86.98 0 top
NOREF#123  -  []  121.82 65.68 90 top
NOREF#124  -  []  115.65 76.63 90 top
NOREF#125  -  []  71.36 12.41 0 top
NOREF#126  -  []  51.01 38.18 90 top
NOREF#127  -  []  73.9 7.91 0 top
NOREF#128  -  []  3.06 7.91 0 top
NOREF#129  -  []  38.31 -1.65 0 top
NOREF#130  -  []  122.69 51 0 top
NOREF#131  -  []  11.59 5.24 0 top
NOREF#132  -  []  5.73 76.71 90 top
NOREF#133  -  []  31.26 83.06 0 top
NOREF#134  -  []  -362.35 -245.44 0 top
NOREF#135  -  []  4.74 78.08 90 top
NOREF#136  -  []  122.99 56.73 90 top
NOREF#137  -  []  115.27 23.13 90 top
NOREF#138  -  []  24.37 83.07 0 top
NOREF#139  -  []  35.21 80.01 90 top
NOREF#140  -  []  84.49 48.71 0 top
NOREF#141  -  []  50.74 40.12 0 top
NOREF#142  -  []  62.51 27.1 0 top
NOREF#143  -  []  9.63 47.36 90 top
NOREF#144  -  []  64.38 46.81 0 top
NOREF#145  -  []  135.25 47.2 0 top
NOREF#146  -  []  92.49 48.71 90 top
NOREF#147  -  []  55.34 -0.64 90 top
NOREF#148  -  []  47.44 24.73 0 top
NOREF#149  -  []  52.36 0.11 0 top
NOREF#150  -  [unnamed#2]  8.42 81.35 0 top
NOREF#151  -  []  38.12 18.88 0 top
NOREF#152  -  []  23.46 0.27 90 top
NOREF#153  -  []  39.82 83.42 0 top
NOREF#154  -  []  38.51 4.45 90 top
NOREF#155  -  []  40.12 48.54 0 top
NOREF#156  -  []  59.17 34.52 0 top
NOREF#157  -  []  33.94 19.17 0 top
NOREF#158  -  []  79.53 76.44 90 top
NOREF#159  -  []  103.31 9.54 0 top
NOREF#160  -  []  23.3 38.12 90 top
NOREF#161  -  []  11.2 48.91 90 top
NOREF#162  -  []  122.99 57.75 90 top
NOREF#163  -  []  46.65 22.43 90 top
NOREF#164  -  []  -108.37 -181.67 0 top
NOREF#165  -  []  95.54 77.36 0 top
NOREF#166  -  []  11.23 47.36 0 top
NOREF#167  -  []  129.17 43.96 90 top
NOREF#168  -  []  133.89 33.2 90 top
NOREF#169  -  []  29.1 61.42 90 top
NOREF#170  -  []  51.51 40 0 top
NOREF#171  -  []  34.99 18.12 90 top
NOREF#172  -  []  27.11 18.15 0 top
NOREF#173  -  []  134.45 7.23 90 top
NOREF#174  -  []  120.27 68.41 0 top
NOREF#175  -  []  95.92 45.03 90 top
NOREF#176  -  []  40.12 48.54 90 top
NOREF#177  -  []  114.1 11.73 0 top
NOREF#178  -  []  100.91 -2.21 90 top
NOREF#179  -  []  125.11 47.55 0 top
NOREF#180  -  []  52.36 6.07 0 top
NOREF#181  -  []  122.99 58.77 90 top
NOREF#182  -  []  73.9 78.76 0 top
NOREF#183  -  []  4.31 77.01 90 top
NOREF#184  -  []  115.65 76.63 0 top
NOREF#185  -  []  29.07 63.23 0 top
NOREF#186  -  []  122.37 57.75 0 top
NOREF#187  -  []  71.36 10.71 90 top
NOREF#188  -  []  50.74 38.07 90 top
NOREF#189  -  []  36.37 18.98 0 top
NOREF#190  -  []  68.61 27.05 90 top
NOREF#191  -  []  17.56 7.05 0 top
NOREF#192  -  []  52.36 0.11 90 top
NOREF#193  -  []  37.94 35.62 0 top
NOREF#194  -  []  3.89 7.24 0 top
NOREF#195  -  []  24.33 -2.66 0 top
NOREF#196  -  []  62.86 35.63 90 top
NOREF#197  -  []  66.99 12.84 90 top
NOREF#198  -  []  121.45 66.73 90 top
NOREF#199  -  []  125.66 61.8 0 top
NOREF#200  -  []  10.81 1.14 0 top
NOREF#201  -  []  68.56 27.95 90 top
NOREF#202  -  []  11.59 5.24 90 top
NOREF#203  -  []  16.91 5.24 0 top
NOREF#204  -  []  21.45 39.69 0 top
NOREF#205  -  []  41.89 6.42 0 top
NOREF#206  -  []  77.77 39.98 0 top
NOREF#207  -  []  66.3 6.5 0 top
NOREF#208  -  []  5.73 5.86 90 top
NOREF#209  -  []  115.87 76.82 0 top
NOREF#210  -  []  61.37 34.85 90 top
NOREF#211  -  []  37.58 0.27 90 top
NOREF#212  -  []  28.43 80.74 90 top
NOREF#213  -  []  66.3 1.5 90 top
NOREF#214  -  []  132.04 32.25 90 top
NOREF#215  -  []  61.38 35.73 90 top
NOREF#216  -  []  28.75 61.28 0 top
NOREF#217  -  []  12.26 5.94 0 top
NOREF#218  -  []  129.17 44.95 0 top
NOREF#219  -  []  127.42 23.72 0 top
NOREF#220  -  []  81.88 51.42 90 top
NOREF#221  -  []  99.81 11.54 0 top
NOREF#222  -  []  33.29 19.42 0 top
NOREF#223  -  []  99.81 8.34 0 top
NOREF#224  -  []  24.27 82.34 0 top
NOREF#225  -  []  79.08 73.12 90 top
NOREF#226  -  []  40.17 49.54 90 top
NOREF#227  -  []  39.61 61.96 0 top
NOREF#228  -  []  64.38 46.81 90 top
NOREF#229  -  []  115.87 76.82 90 top
NOREF#230  -  []  38.04 34.82 90 top
NOREF#231  -  []  115.49 23.38 90 top
NOREF#232  -  []  48.3 1.45 90 top
NOREF#233  -  []  24.93 1.14 0 top
NOREF#234  -  []  23.05 38.34 90 top
NOREF#235  -  []  127.42 23.72 90 top
NOREF#236  -  []  67.44 11.99 0 top
NOREF#237  -  []  15.31 8.89 90 top
NOREF#238  -  []  36.92 18.88 0 top
NOREF#239  -  []  34.53 -2.66 90 top
NOREF#240  -  []  75.58 78.08 90 top
NOREF#241  -  []  65.42 26.71 0 top
NOREF#242  -  []  122.62 52.67 0 top
NOREF#243  -  []  94.61 46.34 90 top
NOREF#244  -  []  67.71 27.1 90 top
NOREF#245  -  []  107.86 40.06 90 top
NOREF#246  -  []  25.24 15.48 90 top
NOREF#247  -  []  130.99 34.25 0 top
NOREF#248  -  []  122.8 51.17 0 top
NOREF#249  -  []  52.36 0.11 90 top
NOREF#250  -  []  25.24 18.42 0 top
NOREF#251  -  []  122.74 52.83 0 top
NOREF#252  -  []  134.1 11.73 90 top
NOREF#253  -  []  122.48 57.91 0 top
NOREF#254  -  []  25.7 5.24 0 top
NOREF#255  -  []  114.85 6.7 0 top
NOREF#256  -  []  46.66 4.45 90 top
NOREF#257  -  []  29.4 8.89 90 top
NOREF#258  -  []  79.53 79.84 0 top
NOREF#259  -  []  75.15 6.16 90 top
NOREF#260  -  []  122.37 56.73 0 top
NOREF#261  -  []  12.91 5.24 0 top
NOREF#262  -  []  110.62 31.41 0 top
NOREF#263  -  []  10.81 1.14 90 top
NOREF#264  -  []  46.65 25.02 0 top
NOREF#265  -  []  133.35 6.7 90 top
NOREF#266  -  []  10.78 47.5 0 top
NOREF#267  -  []  24.93 1.14 90 top
NOREF#268  -  []  122.69 50.04 0 top
NOREF#269  -  []  115.27 23.13 0 top
NOREF#270  -  []  122.37 58.77 0 top
NOREF#271  -  []  113.1 14.53 0 top
NOREF#272  -  []  21.45 39.69 0 top
NOREF#273  -  []  112.23 59.02 90 top
NOREF#274  -  []  0 78.34 0 top
NOREF#275  -  []  26.68 7.05 0 top
NOREF#276  -  []  37.94 33.52 90 top
NOREF#277  -  []  66 8.65 0 top
NOREF#278  -  []  28.98 10.11 0 top
NOREF#279  -  []  99.96 -0.11 90 top
NOREF#280  -  []  65.74 26.81 90 top
NOREF#281  -  []  80.57 45.03 0 top
NOREF#282  -  []  12.56 7.05 0 top
NOREF#283  -  []  39.3 60.56 0 top
NOREF#284  -  []  75.15 77.01 90 top
NOREF#285  -  []  135.1 5.53 90 top
NOREF#286  -  []  103.31 2.54 0 top
NOREF#287  -  []  39.82 78.32 90 top
NOREF#288  -  []  123.32 51 90 top
NOREF#289  -  []  60.21 35.6 0 top
NOREF#290  -  []  128.87 23.94 0 top
NOREF#291  -  []  39.99 34.02 90 top
NOREF#292  -  []  29.19 9.9 0 top
NOREF#293  -  []  15.3 9.5 90 top
NOREF#294  -  []  21.52 57.92 180 bottom
NOREF#295  -  []  22.21 61.65 180 bottom
NOREF#296  -  [unnamed#2]  7.2 79.52 180 bottom
NOREF#297  -  []  50.49 68.11 180 bottom
NOREF#298  -  []  37.25 63.6 180 bottom
NOREF#299  -  [unnamed#2]  8.38 11.02 180 bottom
NOREF#300  -  [unnamed#2]  132.61 5.41 180 bottom
Q301  NX3008NBKW,115  [SC70_3]  74.07 16.07 0 top
Q302  NX3008NBKW,115  [SC70_3]  52.79 23.44 90 top
Q901  NX3008NBKW,115  [SC70_3]  119.94 22.29 180 top
Q902  NX3008NBKW,115  [SC70_3]  135.24 24.06 180 top
Q1401  NX3008NBKW,115  [SC70_3]  77.02 84 270 top
Q1402  NX3008NBKW,115  [SC70_3]  84.21 72.86 90 top
Q1403  NX3008NBKW,115  [SC70_3]  78.89 73 0 top
Q1404  NX3008NBKW,115  [SC70_3]  15.96 67.1 90 top
Q1405  NX3008NBKW,115  [SC70_3]  8.81 67.78 0 top
Q1406  AO7401  [SC70_3]  29.71 54.49 270 top
Q1407  NX3008NBKW,115  [SC70_3]  10.36 62.62 0 top
Q1408  NX3008NBKW,115  [SC70_3]  21.57 64.75 270 top
Q1409  NX3008NBKW,115  [SC70_3]  19.17 19.2 270 top
Q1410  NX3008NBKW,115  [SC70_3]  8.46 58.99 0 top
Q1411  NX3008NBKW,115  [SC70_3]  7.36 62.63 0 top
QZ401  32.768KHZ  [XTAL2-3P2X1P5-SM]  84.05 63.81 0 bottom
QZ701  32.768KHZ  [XTAL2-3P2X1P5-SM]  57.29 26.96 90 top
R14  10K  [0402_CC]  77.15 77.16 90 bottom
R16  0  [0402_CC]  75.59 74.45 90 bottom
R64  4.7K  [RC0402_25]  71.72 21.42 270 top
R65  4.7K  [RC0402_25]  72.69 21.43 270 top
R102  0  [RC0402_25]  72.72 47.17 0 bottom
R111  0  [0603_CC]  60.05 22.28 270 bottom
R163  0  [0402_CC]  117.04 68.41 180 top
R164  0  [0402_CC]  117.08 63.3 180 top
R201  10K  [0402_CC]  69.56 47.28 0 bottom
R204  120  [0402_CC]  83.7 53.82 90 bottom
R205  150  [0402_CC]  73.22 49.49 270 bottom
R207  10K  [0402_CC]  72.33 53.44 0 bottom
R208  10K  [0402_CC]  73.4 52.2 180 bottom
R209  240 OHM  [0201_CC]  77.86 52.78 0 bottom
R210  0  [0402_CC]  73.85 55.29 270 bottom
R211  240 OHM  [0201_CC]  77.97 50.91 180 bottom
R213  10K  [0402_CC]  53.2 41.97 270 top
R301  0  [0201_CC]  23.62 29.69 90 top
R302  0  [0805_CC]  44.99 21.85 180 top
R303  200  [0201_CC]  83.87 61.03 180 top
R304  1M  [0402_CC]  50.08 23.51 180 top
R305  100K  [0402_CC]  50.08 22.05 180 top
R306  4.7K  [0402_CC]  102.83 57.88 0 top
R307  4.7K  [0402_CC]  102.83 62.21 0 top
R308  4.7K  [0402_CC]  102.83 59.01 0 top
R309  4.7K  [0402_CC]  102.83 63.37 0 top
R310  10K  [0402_CC]  121.22 51.83 180 top
R311  10K  [0402_CC]  121.23 55.56 180 top
R312  4.7K  [0402_CC]  89.81 48.79 180 bottom
R313  10K  [0402_CC]  66.3 15.98 90 top
R350  0  [0402_CC]  71.47 4.52 0 top
R351  0  [0402_CC]  64.34 8.14 0 top
R352  0  [0402_CC]  71.47 2.74 0 top
R353  0  [0402_CC]  71.48 7.05 180 top
R354  0  [0402_CC]  64.34 5.79 0 top
R355  0  [0402_CC]  64.19 2.15 180 top
R356  0  [0402_CC]  71.47 3.78 0 top
R357  0  [0402_CC]  64.19 3.35 180 top
R358  0  [0402_CC]  71.48 5.95 180 top
R359  0  [0402_CC]  64.34 6.99 0 top
R360  4.7K  [RC0402_25]  27.96 29.59 90 top
R401  100K  [0402_CC]  50.96 44.31 270 top
R402  100K  [0402_CC]  82.76 64.69 0 top
R403  100K  [0402_CC]  56.99 76.51 0 top
R404  0  [0201_CC]  98.37 64.31 90 top
R405  10K  [0402_CC]  83.36 42.61 270 top
R406  0  [0201_CC]  86.98 63.03 270 bottom
R407  0  [0201_CC]  86.42 62.06 180 bottom
R408  4.7M  [RC0402_25]  85.25 62.08 180 top
R409  510K  [0402_CC]  88.09 65.91 180 bottom
R410  0  [0402_CC]  30.68 19.34 180 top
R411  0  [0402_CC]  30.69 18.23 180 top
R412  100K  [0402_CC]  28.03 13.49 90 top
R413  100K  [0402_CC]  30.69 17.15 180 top
R414  51  [0402_CC]  81.42 42.62 270 top
R415  100K  [0402_CC]  82.78 63.62 180 top
R416  51  [0402_CC]  82.41 42.61 270 top
R417  51  [0402_CC]  128.46 18.23 270 top
R418  100K  [0402_CC]  49.84 44.28 90 top
R419  51  [0402_CC]  124.92 18.38 270 top
R420  0  [0402_CC]  41.41 19.36 0 top
R421  0  [0402_CC]  41.45 15.84 0 top
R423  100K  [0402_CC]  82.79 62.51 180 top
R424  100K  [0402_CC]  89.37 64.13 0 top
R431  10K  [0402_CC]  37.85 21.03 270 top
R432  0  [RC0402_25]  113.55 23.42 0 bottom
R433  0  [RC0402_25]  113.55 24.39 0 bottom
R434  0  [0402_CC]  30.69 14.95 0 top
R501  10K  [0402_CC]  98.18 42.84 180 top
R502  10K  [0402_CC]  97.89 39.45 0 top
R503  0  [0402_CC]  93.68 29.85 180 top
R504  510  [0402_CC]  80.26 22.45 90 top
R505  10K  [0402_CC]  83.19 37.31 0 top
R506  10K  [0402_CC]  93.68 28.7 180 top
R507  510  [0402_CC]  77.85 22.45 90 top
R508  2.49K  [0402_CC]  83.82 27.11 180 top
R509  1M  [1206_CC]  96.68 18.31 270 top
R510  0  [0402_CC]  80.26 33.02 0 top
R511  510K  [0402_CC]  84.46 30.58 90 top
R512  4.7K  [RC0402_25]  83.06 35.28 0 top
R513  4.7K  [RC0402_25]  83.06 32.49 0 top
R514  4.7K  [RC0402_25]  91.95 39.22 270 top
R515  4.7K  [RC0402_25]  92.96 39.22 270 top
R516  4.7K  [RC0402_25]  87.88 39.34 270 top
R517  4.7K  [RC0402_25]  89.92 39.22 270 top
R518  4.7K  [RC0402_25]  90.93 39.22 270 top
R519  4.7K  [RC0402_25]  83.06 36.17 180 top
R520  4.7K  [RC0402_25]  83.06 33.38 180 top
R521  4.7K  [RC0402_25]  83.06 34.26 180 top
R522  4.7K  [RC0402_25]  91.99 36.55 90 top
R523  4.7K  [RC0402_25]  93.01 36.55 90 top
R524  4.7K  [RC0402_25]  87.93 36.55 90 top
R525  4.7K  [RC0402_25]  88.94 36.55 90 top
R526  4.7K  [RC0402_25]  89.96 36.55 90 top
R527  4.7K  [RC0402_25]  90.97 36.55 90 top
R529  510  [0402_CC]  80.67 35.66 0 top
R530  0  [0603_CC]  96.32 35.36 90 top
R531  0  [0603_CC]  94.08 34.73 180 top
R601  4.7K  [RC0402_25]  46.39 54.94 180 top
R602  4.7K  [RC0402_25]  46.39 53.59 180 top
R603  4.7K  [RC0402_25]  46.39 52.24 180 top
R604  4.7K  [RC0402_25]  46.39 50.9 180 top
R605  1K  [0402_CC]  36.37 57.28 180 top
R606  1K  [0402_CC]  36.37 54.06 180 top
R607  1K  [0402_CC]  36.37 52.88 180 top
R608  1K  [0402_CC]  36.37 50.55 180 top
R609  100K  [0402_CC]  36.37 49.48 180 top
R610  100K  [0402_CC]  36.37 51.7 180 top
R611  100K  [0402_CC]  36.37 55.09 180 top
R612  100K  [0402_CC]  36.37 56.19 180 top
R613  1.0K  [0402_CC]  6.46 70.4 270 top
R701  0  [0402_CC]  72.38 34.02 180 top
R702  0  [0603_CC]  63.45 42.29 0 top
R703  100K  [0402_CC]  59.29 30.88 0 top
R704  0  [0603_CC]  68.35 42.36 180 top
R705  100K  [0402_CC]  71.34 24 90 top
R706  0  [0402_CC]  59.29 29.93 0 top
R707  0  [0402_CC]  72.38 36.13 180 top
R708  0  [0402_CC]  72.38 37.19 180 top
R709  0  [0603_CC]  75.03 29.27 270 top
R710  0  [0402_CC]  72.66 23.99 90 top
R711  0  [0402_CC]  72.38 35.08 0 top
R712  0  [0201_CC]  69.7 23.95 270 top
R713  0  [0201_CC]  70.34 23.97 270 top
R714  0  [0402_CC]  72.39 38.26 180 top
R715  0  [0402_CC]  72.4 39.34 180 top
R716  0  [0402_CC]  72.08 26.49 180 top
R717  0  [0201_CC]  68.98 23.95 90 top
R718  0  [0402_CC]  72.08 25.42 0 top
R719  0  [0201_CC]  68.27 23.96 90 top
R720  1M  [0201_CC]  59.34 27.55 270 top
R723  0  [0402_CC]  58.31 24.15 180 top
R741  0  [RC0402_25]  113.66 21.63 270 bottom
R742  0  [RC0402_25]  118.92 23.73 0 bottom
R743  56K  [RC0402_25]  117.08 27.47 270 bottom
R744  47K  [RC0402_25]  114.95 27.52 90 bottom
R745  33 OHM  [RC0402_25]  126.18 70.48 0 top
R746  10K  [0402_CC]  116.06 27.49 90 bottom
R751  0  [RC0402_25]  114.78 21.63 270 bottom
R752  0  [RC0402_25]  118.95 22.77 0 bottom
R801  2.2K  [0402_CC]  104.46 60.14 0 top
R802  2.2K  [0402_CC]  104.46 61.19 0 top
R804  10K  [0402_CC]  104.46 64.35 0 top
R805  100  [RC0402_25]  106.1 57.17 270 top
R806  100  [RC0402_25]  108.13 57.17 270 top
R807  100  [RC0402_25]  107.11 57.17 270 top
R808  10K  [0402_CC]  101 67.95 270 top
R809  100  [RC0402_25]  109.14 57.17 270 top
R810  100  [RC0402_25]  111.18 57.17 270 top
R811  0  [0402_CC]  104.46 66.51 0 top
R812  100  [RC0402_25]  110.16 57.17 270 top
R813  0  [0402_CC]  104.46 56.94 0 top
R817  10K  [0402_CC]  116.89 61.09 180 top
R818  100  [RC0402_25]  114.63 60.17 0 top
R820  0  [0402_CC]  104.46 63.33 0 top
R821  15K  [RC0402_25]  114.63 62.2 0 top
R822  100  [RC0402_25]  114.63 61.19 0 top
R823  0  [0402_CC]  104.44 55.84 0 top
R824  0  [0402_CC]  104.46 59.05 0 top
R825  100  [RC0402_25]  114.63 63.22 0 top
R826  100  [RC0402_25]  114.63 65.25 0 top
R827  18K  [RC0402_25]  117.04 62.18 0 top
R828  0  [0402_CC]  104.46 62.26 0 top
R829  100  [RC0402_25]  112.05 66.68 90 top
R830  0  [0402_CC]  104.46 57.98 0 top
R831  100  [RC0402_25]  113.06 66.68 90 top
R832  100  [RC0402_25]  110.01 66.68 90 top
R833  100  [RC0402_25]  111.03 66.68 90 top
R835  100  [RC0402_25]  109 66.68 90 top
R836  100  [RC0402_25]  106.97 66.68 90 top
R837  100  [RC0402_25]  105.95 66.68 90 top
R838  10K  [0402_CC]  132.61 68 270 top
R839  10K  [0402_CC]  129.44 68.12 270 top
R840  10K  [0402_CC]  114.33 69.82 0 top
R841  10K  [0402_CC]  104.19 70.51 0 top
R845  100  [RC0402_25]  114.65 59.24 0 top
R850  100  [RC0402_25]  114.08 79.83 180 bottom
R851  100  [RC0402_25]  108.98 79.8 180 bottom
R852  100  [RC0402_25]  113.46 60.77 90 bottom
R853  100  [RC0402_25]  106.47 79.81 0 bottom
R854  100  [RC0402_25]  105.96 72.91 90 top
R855  0  [0402_CC]  130.06 77.84 270 bottom
R856  0  [0402_CC]  130.9 83.13 180 bottom
R858  100  [RC0402_25]  107.99 66.66 90 top
R860  100  [RC0402_25]  115.02 63.34 270 bottom
R861  0  [0402_CC]  114.15 77.26 0 bottom
R862  0  [0402_CC]  115.86 75.15 90 bottom
R863  100K  [0402_CC]  118.15 77.28 270 bottom
R871  0  [0402_CC]  59.52 35.23 180 bottom
R901  3.3  [0603_CC]  35.94 39.47 90 top
R902  187K  [0402_CC]  130.11 36.74 270 top
R903  1K  [0402_CC]  128.73 29.67 0 top
R904  10K  [0603_CC]  59.99 7.31 180 top
R905  0  [1206_CC]  62.2 2.76 270 top
R906  43K  [0402_CC]  43.79 34.97 0 top
R907  10K  [0402_CC]  36.18 32.41 0 top
R908  100K  [0402_CC]  36.12 36.75 180 top
R909  0  [0402_CC]  126.36 27.15 270 top
R910  5.6K  [0402_CC]  36.28 34.25 180 top
R911  100K  [0402_CC]  43.82 36.12 0 top
R912  100  [RC0805_OV]  48.82 35.81 90 top
R913  100K  [0402_CC]  50.25 36.3 270 top
R914  1K  [0402_CC]  48.76 32.89 270 top
R915  1K  [0402_CC]  52.07 41.98 270 top
R917  10K  [0402_CC]  119.87 9.1 270 bottom
R918  4.7K  [RC0402_25]  120.88 18.65 90 top
R919  0  [0402_CC]  119.68 18.77 90 top
R922  1K  [0402_CC]  128.73 33.01 0 top
R923  10K  [0402_CC]  126.89 4.34 270 top
R924  10K  [0402_CC]  129.56 18.15 270 top
R930  0  [0402_CC]  117.11 18.74 270 top
R931  0  [0402_CC]  118.13 18.71 270 top
R932  0  [0402_CC]  116.17 18.71 90 top
R935  100K  [0402_CC]  118.92 29.01 0 top
R936  10K  [0402_CC]  116.17 20.47 270 top
R938  0  [0402_CC]  120.7 26.31 90 top
R941  0  [0402_CC]  121.78 26.29 90 bottom
R942  0  [0402_CC]  121.79 26.3 90 top
R943  0  [0402_CC]  123.99 26.28 90 top
R944  0  [0402_CC]  122.88 26.28 90 top
R945  0  [0402_CC]  120.69 26.31 90 bottom
R946  0  [0402_CC]  131.2 21.79 270 top
R947  0  [0402_CC]  130.13 21.76 270 top
R948  0  [0402_CC]  129.05 21.75 270 top
R949  0  [0402_CC]  128 21.76 270 top
R950  1K  [0402_CC]  128.73 31.86 0 top
R951  10K  [0402_CC]  130.93 4.12 90 top
R952  10K  [0402_CC]  132.32 4.12 90 top
R953  0  [0402_CC]  135.95 27.05 180 top
R954  100K  [0402_CC]  132.87 25.87 90 top
R956  0  [0402_CC]  115.1 20.48 90 top
R957  100  [RC0402_25]  115.1 18.63 270 top
R958  0  [0402_CC]  122.07 23.01 270 top
R959  0  [0402_CC]  120.21 24.65 180 top
R1008  0  [0402_CC]  64.35 12.29 0 top
R1009  0  [0402_CC]  64.35 15.45 0 top
R1015  0  [0402_CC]  64.35 11.17 0 top
R1016  0  [0402_CC]  64.35 14.38 0 top
R1017  0  [0402_CC]  64.35 10.1 0 top
R1018  0  [0402_CC]  64.35 13.44 0 top
R1051  0  [0402_CC]  121.21 48.5 0 top
R1052  10K  [0402_CC]  137.77 40.94 270 top
R1053  10K  [0402_CC]  135 44.6 270 top
R1054  10K  [0402_CC]  131.45 40.01 0 top
R1055  0  [0603_CC]  121.72 54.16 0 top
R1056  10K  [0402_CC]  136.15 44.68 270 top
R1057  0  [0402_CC]  137.41 44.73 90 top
R1060  0  [0402_CC]  121.21 56.65 0 top
R1061  0  [0402_CC]  121.21 52.86 0 top
R1062  0  [0402_CC]  121.21 50.83 0 top
R1063  0  [0402_CC]  121.21 49.77 0 top
R1064  0  [0402_CC]  121.21 59.21 0 top
R1065  0  [0402_CC]  121.21 57.85 0 top
R1072  1K  [0402_CC]  40.44 55.43 180 bottom
R1073  0  [0402_CC]  45.84 51.92 180 bottom
R1074  0  [0402_CC]  45.84 48.46 180 bottom
R1075  10K  [0402_CC]  36.89 49.87 0 bottom
R1076  10K  [0402_CC]  36.89 48.8 0 bottom
R1077  10K  [0402_CC]  45.84 54.03 180 bottom
R1078  10K  [0402_CC]  45.84 50.86 180 bottom
R1079  10K  [0402_CC]  45.84 49.52 180 bottom
R1080  10K  [0402_CC]  45.84 52.98 180 bottom
R1081  10K  [0402_CC]  35.46 48.4 270 bottom
R1082  0  [0402_CC]  37.41 56.64 0 bottom
R1083  330  [RC0402_25]  37.9 54.45 270 bottom
R1084  0  [0402_CC]  38.21 49.33 270 bottom
R1085  0  [0402_CC]  36.89 47.18 180 bottom
R1202  100K  [0402_CC]  99.54 15.94 270 top
R1203  100K  [0402_CC]  99.53 17.46 90 top
R1204  0  [0402_CC]  113.05 36.35 0 top
R1205  0  [0402_CC]  107.78 26.6 180 top
R1206  0  [0402_CC]  107.78 29.55 180 top
R1207  0  [0402_CC]  107.78 27.58 180 top
R1208  0  [0402_CC]  107.78 28.56 180 top
R1209  0  [0402_CC]  101.92 31.43 270 top
R1211  0  [0402_CC]  107.78 30.53 180 top
R1212  0  [0402_CC]  107.78 31.51 180 top
R1214  0  [0402_CC]  107.78 25.62 0 top
R1216  0  [0402_CC]  107.78 22.67 0 top
R1218  0  [0402_CC]  107.78 24.64 0 top
R1219  0  [0402_CC]  113.05 34.29 0 top
R1220  0  [0402_CC]  107.78 23.65 0 top
R1221  100K  [0402_CC]  113.06 35.33 180 top
R1222  10K  [0402_CC]  113.04 33.27 180 top
R1302  51  [0402_CC]  1.81 6.23 90 top
R1303  51  [0402_CC]  74 2.05 270 top
R1318  51  [0402_CC]  1.9 77.03 270 top
R1322  51  [0402_CC]  72.55 77.38 270 top
R1324  22  [0402_CC]  1.67 8.87 270 top
R1325  22  [0402_CC]  76.29 11.69 180 top
R1326  22  [0402_CC]  1.9 80 90 top
R1327  22  [0402_CC]  72.52 80.35 90 top
R1329  15K  [RC0402_25]  9.75 73.77 90 top
R1330  12K  [RC0402_25]  8.69 73.77 270 top
R1333  10.0K  [0201_CC]  8.43 77.87 90 top
R1401  1K  [0402_CC]  117.05 66.19 0 top
R1402  4.7K  [RC0402_25]  116.92 70.65 0 top
R1403  4.7K  [RC0402_25]  117.01 65.3 0 top
R1404  4.7K  [RC0402_25]  116.92 69.56 0 top
R1405  2.2K  [0402_CC]  122.48 72.75 270 top
R1406  2.2K  [0402_CC]  119.02 72.74 270 top
R1407  2.2K  [0402_CC]  94.55 72.74 270 top
R1408  2.2K  [0402_CC]  92.04 72.74 270 top
R1409  0  [0402_CC]  119.32 63.61 90 top
R1410  0  [0402_CC]  120.68 63.61 90 top
R1411  0  [0402_CC]  117.06 64.37 0 top
R1412  0  [0402_CC]  121.88 63.64 90 top
R1413  0  [0402_CC]  117.04 67.29 0 top
R1414  0  [0402_CC]  90.86 72.68 90 top
R1415  0  [0402_CC]  120.16 72.68 90 top
R1416  0  [0402_CC]  93.45 72.68 90 top
R1417  0  [0402_CC]  121.35 72.68 90 top
R1418  100  [RC0402_25]  30.72 58.84 90 top
R1419  100  [RC0402_25]  31.73 58.89 90 top
R1420  1K  [0402_CC]  123.12 63.59 90 top
R1421  1K  [0402_CC]  9.74 40.57 270 top
R1422  2.2K  [0402_CC]  4.82 46.68 90 top
R1423  330  [RC0402_25]  82.02 74.34 270 top
R1424  330  [RC0402_25]  80.58 82.05 90 top
R1425  330  [RC0402_25]  80.9 74.31 270 top
R1426  0  [0402_CC]  22.33 82.27 180 top
R1427  0  [0402_CC]  37.56 81.72 0 top
R1428  0  [0402_CC]  1.56 39.76 270 top
R1429  1K  [0402_CC]  87.7 73.14 270 top
R1430  0  [0402_CC]  13 61.19 180 top
R1431  100K  [0402_CC]  53.21 78.06 90 top
R1432  100K  [0402_CC]  56.6 78.06 90 top
R1433  10K  [0402_CC]  86.56 73.14 90 top
R1434  10K  [0402_CC]  74.42 84.37 270 top
R1435  10K  [0402_CC]  76.37 73.85 180 top
R1436  100K  [0402_CC]  54.34 78.06 270 top
R1437  100K  [0402_CC]  55.39 78.06 270 top
R1438  1K  [0402_CC]  73.3 84.37 90 top
R1439  1K  [0402_CC]  76.37 74.96 0 top
R1440  187K  [0402_CC]  48.78 68.92 0 top
R1441  187K  [0402_CC]  48.78 66.67 0 top
R1442  100  [RC0402_25]  60.17 66.82 0 top
R1443  0  [0402_CC]  64.95 72.68 90 top
R1444  100  [RC0402_25]  60.24 65.6 0 top
R1445  0  [0402_CC]  67.46 72.68 90 top
R1446  187K  [0402_CC]  48.76 67.79 180 top
R1447  187K  [0402_CC]  48.76 65.46 180 top
R1448  0  [0402_CC]  48.77 63.63 180 top
R1449  0  [0402_CC]  28.42 51.79 270 top
R1450  10K  [0402_CC]  11.73 64.86 180 top
R1451  10K  [0402_CC]  24.17 64.92 180 top
R1452  10K  [0402_CC]  19.64 21.61 270 top
R1453  1K  [0402_CC]  5.13 58.97 180 top
R1454  100  [RC0402_25]  30.97 51.73 270 top
R1455  100  [RC0402_25]  9.81 64.87 0 top
R1456  100  [RC0402_25]  18.45 21.61 270 top
R1457  100  [RC0402_25]  24.18 63.8 180 top
R1458  100  [RC0402_25]  6.47 59.19 90 top
R1459  10K  [0402_CC]  30.74 41.28 90 top
R1460  10K  [0402_CC]  26.89 41.4 90 top
R1461  10K  [0402_CC]  25.46 41.4 90 top
R1462  0  [0402_CC]  26.45 51.79 90 top
R1463  0  [0402_CC]  25.27 51.79 90 top
R1464  1K  [0402_CC]  5.18 49.97 180 top
R1465  1K  [0402_CC]  6.04 56.34 180 top
R1467  1K  [0402_CC]  6.16 65.4 180 top
R1468  1K  [0402_CC]  5.22 61.93 180 top
R1469  0  [0402_CC]  18.08 52.56 90 top
R1470  0  [0402_CC]  16.9 52.56 90 top
R1485  10K  [0402_CC]  16.67 55.24 0 top
R1486  10K  [0402_CC]  22.67 52.69 90 top
R1487  0  [0402_CC]  21.61 52.69 90 top
R1488  5.1K  [RC0402_25]  13.95 9.48 90 top
R1489  5.1K  [RC0402_25]  17.29 9.56 90 top
R1490  10K  [0402_CC]  16.67 56.33 180 top
R1501  0  [0402_CC]  30.43 77.42 90 top
R1502  0  [0402_CC]  30.4 67.49 270 top
R1503  0  [0603_CC]  40.76 76.67 270 top
R1504  62.0  [0603_CC]  38.01 66.62 90 top
R1505  2.2K  [0402_CC]  26.19 77.42 270 top
R1506  1K  [0402_CC]  32.69 77.42 270 top
R1507  0  [0402_CC]  39.48 66.79 90 top
R1508  0  [0402_CC]  31.6 77.42 270 top
R1509  0  [0402_CC]  27.32 77.42 270 top
R1510  0  [0402_CC]  45.08 66.54 90 top
R1511  62.0  [0603_CC]  46.46 66.21 270 top
R1512  10K  [0402_CC]  31.65 67.5 90 top
R1703  0  [0402_CC]  22.24 71.93 0 top
R1704  0  [0402_CC]  23.15 68.69 90 top
R1705  0  [0402_CC]  24.25 68.69 90 top
R1706  10K  [0402_CC]  24.06 74.84 90 top
R1717  10K  [0402_CC]  14.01 50.15 0 top
R1718  10K  [0402_CC]  13.3 51.49 90 top
R1719  10K  [0402_CC]  14.02 45.3 0 top
R1720  0  [0402_CC]  12.2 51.49 90 top
R1721  0  [0402_CC]  11.07 51.49 90 top
R1723  0  [0402_CC]  8.91 51.49 90 top
R1724  0  [0402_CC]  7.8 51.49 90 top
R1726  2.2K  [0402_CC]  19.18 28.3 0 top
R1727  2.2K  [0402_CC]  19.17 29.38 0 top
R1728  10K  [0402_CC]  27.76 58.89 270 top
R1729  1K  [0402_CC]  12.61 40.5 270 top
R1730  1K  [0402_CC]  7.2 39.7 270 top
R1731  100  [RC0402_25]  28.86 58.84 90 top
R1732  100  [RC0402_25]  29.78 58.84 90 top
R1733  1K  [0402_CC]  4.77 51.95 0 top
R1734  10K  [0402_CC]  5.92 46.75 270 top
R1735  10K  [0402_CC]  2.62 39.76 90 top
R1736  10K  [0402_CC]  3.82 39.76 90 top
R1737  10K  [0402_CC]  16.55 19.05 90 top
R1738  12K  [0402_CC]  10.08 19.15 270 top
R1739  0  [0402_CC]  2.8 46.69 90 top
R1740  0  [0402_CC]  4.93 39.76 270 top
R1741  0  [0402_CC]  13 63.53 180 top
R1742  10K  [0402_CC]  15.34 65.11 180 top
R1743  0  [0402_CC]  20.17 61.23 0 top
R1744  1K  [0402_CC]  13.73 65.09 0 top
R1745  10K  [0402_CC]  20.17 60.13 0 top
R1746  10K  [0402_CC]  20.17 62.33 0 top
